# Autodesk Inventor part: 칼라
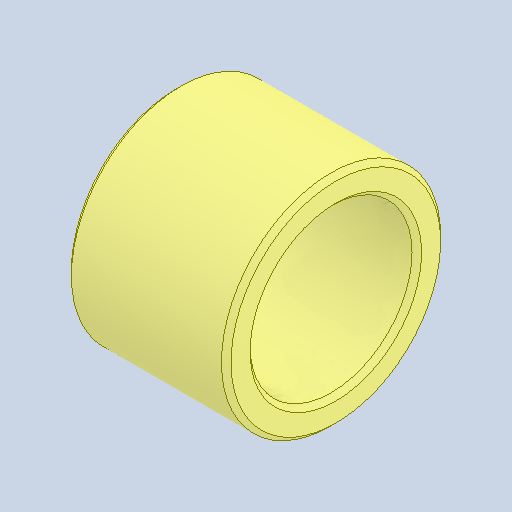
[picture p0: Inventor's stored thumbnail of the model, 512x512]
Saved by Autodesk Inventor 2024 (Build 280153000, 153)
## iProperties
Created: 2026-01
Part Number: 칼라
Material: 강철, 연강
Document SubType Name: Modeling
Designer: 2-10
Density: 7.85 g/cm^3
Appearance: 기본값
Author: jhkim
Sending System: Autodesk Inventor 2026
Preprocessor: ST-DEVELOPER v20.1
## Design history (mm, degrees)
node "칼라1"
node "솔리드2"
node "솔리드1"
